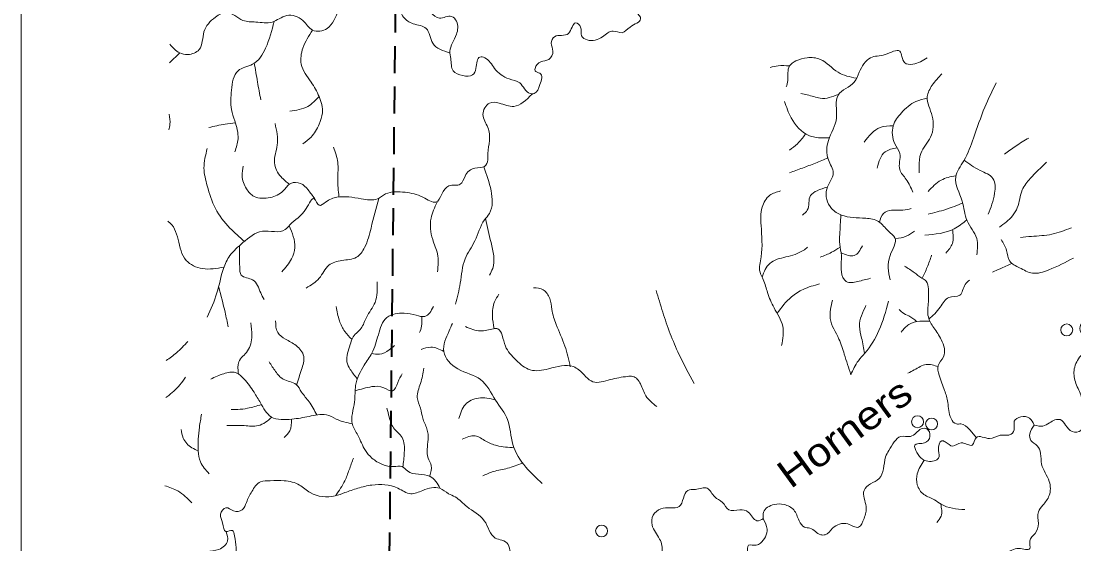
# Model space of a CAD drawing. Extents: x 788888 to 797112, y 8503144 to 8514989.
# Drawn here: x 788888 to 793559, y 8509330 to 8511652 of the extents above; entities that cross this region are included whole.
import ezdxf

# ---------------------------------------------------------------- set-up
doc = ezdxf.new("R2010")
doc.units = 0
doc.header["$LTSCALE"] = 40
doc.linetypes.add('MEDIUM_DASHED', pattern=[4.5, 3, -1.5])
for name, color, linetype, lineweight in [('15', 7, 'Continuous', 13), ('62', 7, 'Continuous', 13), ('63', 7, 'MEDIUM_DASHED', 40)]:
    doc.layers.add(name, color=color, linetype=linetype, lineweight=lineweight)

msp = doc.modelspace()

# ---------------------------------------------------------------- linework, layer by layer
at = {"layer": '15'}
msp.add_line((789591.99, 8511510.53), (789546.97, 8511465.81), dxfattribs=at)
for centre in [(793526.77, 8510280.71), (792864.9, 8509872.72), (792927.25, 8509863.12), (791463.47, 8509387.93)]:
    msp.add_circle(centre, 26.35, dxfattribs=at)
for points in [[(792948.03, 8512205.24), (792917.26, 8512179.9), (792888.48, 8512147.5), (792874.09, 8512140.3), (792838.12, 8512140.3), (792787.76, 8512118.7), (792748.2, 8512104.3), (792708.63, 8512086.3), (792683.45, 8512057.5), (792654.67, 8512035.9), (792597.12, 8512035.9), (792553.95, 8512050.3), (792532.37, 8512100.7), (792550.35, 8512136.7), (792553.95, 8512158.3), (792485.61, 8512158.3), (792449.64, 8512147.5), (792413.66, 8512115.1), (792374.1, 8512104.3), (792338.13, 8512082.7), (792312.95, 8512046.7), (792258.99, 8512064.7), (792215.82, 8512075.5), (792172.66, 8512061.1), (792169.06, 8512025.1), (792176.26, 8511985.51), (792161.87, 8511920.71), (792111.51, 8511852.31), (792050.36, 8511819.91), (791960.43, 8511812.71), (791892.08, 8511783.91), (791802.16, 8511776.71), (791744.6, 8511733.51), (791719.42, 8511701.11), (791690.65, 8511711.91), (791661.87, 8511744.31), (791633.09, 8511765.91), (791611.51, 8511758.71), (791586.33, 8511733.51), (791579.14, 8511711.91), (791615.11, 8511690.31), (791636.69, 8511661.51), (791589.93, 8511625.51), (791553.96, 8511600.32), (791514.39, 8511607.52), (791467.63, 8511582.32), (791399.28, 8511567.92), (791374.1, 8511585.92), (791370.5, 8511625.51), (791348.92, 8511643.51), (791316.55, 8511596.72), (791254.68, 8511582.32), (791240.29, 8511553.52), (791247.48, 8511517.52), (791229.5, 8511481.52), (791193.52, 8511470.72), (791168.35, 8511441.92), (791168.35, 8511431.12), (791189.93, 8511420.32), (791189.93, 8511369.92), (791164.75, 8511330.32), (791146.76, 8511330.32), (791100, 8511377.12), (791053.24, 8511395.12), (790988.49, 8511441.92), (790945.32, 8511488.72), (790923.74, 8511492.32), (790905.76, 8511441.92), (790891.37, 8511413.12), (790848.2, 8511409.52), (790805.04, 8511431.12), (790794.25, 8511485.12), (790790.65, 8511517.52), (790819.43, 8511593.12), (790819.43, 8511650.71), (790797.84, 8511672.31), (790743.89, 8511665.11), (790707.92, 8511690.31), (790689.93, 8511751.51), (790697.12, 8511819.91), (790653.96, 8511845.11), (790610.79, 8511881.11), (790560.43, 8511870.31), (790513.67, 8511938.71), (790477.7, 8511992.71), (790427.34, 8512025.1), (790380.58, 8512039.5), (790333.82, 8512050.3), (790312.23, 8512100.7), (790312.23, 8512172.7), (790305.04, 8512266.3)], [(794022.17, 8512071.41), (794015.97, 8512028.82), (794054.34, 8512024.02), (794078.32, 8512052.82), (794121.49, 8512024.02), (794179.04, 8511966.42), (794217.41, 8511932.82), (794217.41, 8511899.22), (794207.82, 8511860.82), (794164.65, 8511827.22), (794150.27, 8511764.83), (794131.08, 8511716.83), (794097.51, 8511692.83), (794073.53, 8511649.63), (794073.53, 8511620.83), (794035.16, 8511606.43), (794001.59, 8511558.43), (794001.59, 8511520.03), (793924.85, 8511515.23), (793872.09, 8511510.43), (793819.33, 8511467.24), (793795.35, 8511400.04), (793780.96, 8511347.24), (793771.37, 8511323.24), (793742.59, 8511328.04), (793718.61, 8511352.04), (793685.04, 8511347.24), (793670.65, 8511280.04), (793665.86, 8511236.84), (793694.63, 8511236.84), (793709.02, 8511227.24), (793699.43, 8511179.24), (793689.84, 8511136.04), (793675.45, 8511102.45), (793665.86, 8511064.05), (793685.04, 8511044.85), (793689.84, 8511030.45), (793675.45, 8511006.45), (793670.65, 8510972.85), (793694.63, 8510958.45), (793733, 8510972.85), (793756.98, 8510996.85), (793790.56, 8510977.65), (793819.33, 8510967.09), (793843.31, 8510938.29), (793876.89, 8510919.09), (793915.26, 8510919.09), (793958.42, 8510909.49), (793991.99, 8510890.29), (794011.18, 8510861.49), (793996.79, 8510808.69), (794006.38, 8510727.09), (794001.59, 8510626.3), (794015.97, 8510563.9), (794059.14, 8510530.3), (794063.94, 8510491.9), (794049.55, 8510458.3), (794006.38, 8510453.5), (793963.22, 8510487.1), (793910.46, 8510491.9), (793867.29, 8510487.1), (793814.54, 8510487.1), (793776.17, 8510453.5), (793752.19, 8510419.9), (793752.19, 8510391.1), (793718.61, 8510376.7), (793694.63, 8510371.9), (793685.04, 8510343.1), (793651.47, 8510328.71), (793617.9, 8510323.91), (793589.12, 8510304.71), (793589.12, 8510271.11), (793632.28, 8510266.31), (793699.43, 8510275.91), (793728.21, 8510275.91), (793728.21, 8510247.11), (793675.45, 8510218.31), (793627.49, 8510199.11), (793589.12, 8510165.51), (793560.34, 8510107.91), (793565.14, 8510050.31), (793589.12, 8509992.71), (793608.3, 8509935.12), (793617.9, 8509896.72), (793598.71, 8509877.52), (793589.12, 8509834.32), (793550.75, 8509829.52), (793521.97, 8509858.32), (793497.99, 8509882.32), (793450.03, 8509867.92), (793421.25, 8509853.52), (793382.88, 8509858.32)], [(790791, 8511510.51), (790714.06, 8511553.88), (790685.29, 8511618.68), (790627.73, 8511640.28), (790584.57, 8511669.08), (790570.18, 8511726.67), (790570.18, 8511762.67), (790505.43, 8511798.67), (790469.46, 8511798.67), (790440.68, 8511755.47), (790404.71, 8511769.87), (790375.93, 8511762.67), (790332.77, 8511741.07), (790275.22, 8511654.68), (790246.44, 8511618.68), (790181.69, 8511611.48), (790138.53, 8511654.68), (790066.58, 8511676.28), (790001.84, 8511647.48), (789929.89, 8511647.48), (789872.34, 8511654.68), (789800.4, 8511690.67), (789750.04, 8511669.08), (789699.68, 8511604.28), (789678.1, 8511525.08), (789627.74, 8511503.48), (789591.77, 8511510.68), (789547.88, 8511548.92)], [(790011.08, 8511649.28), (789973.06, 8511532.28), (789915.51, 8511460.28), (789850.76, 8511431.48), (789821.98, 8511345.08), (789821.98, 8511258.69), (789836.37, 8511208.29), (789850.76, 8511129.09), (789836.37, 8511071.49)], [(790181.69, 8511611.48), (790138.53, 8511532.28), (790131.33, 8511460.28), (790174.5, 8511381.08), (790210.47, 8511316.29), (790224.86, 8511244.29), (790210.47, 8511193.89), (790174.5, 8511136.29), (790138.53, 8511107.49)], [(792908.29, 8511489.08), (792843.55, 8511460.28), (792807.57, 8511467.48), (792785.99, 8511517.88), (792721.24, 8511503.48), (792656.5, 8511489.08), (792606.14, 8511424.28), (792584.55, 8511381.08), (792512.61, 8511323.48), (792505.42, 8511222.69), (792469.45, 8511121.89), (792469.45, 8511035.49), (792491.03, 8510977.89), (792462.25, 8510905.9), (792483.84, 8510819.5), (792527, 8510790.7), (792634.91, 8510776.3), (792692.47, 8510761.9), (792735.63, 8510718.7), (792764.41, 8510689.9), (792742.83, 8510610.7), (792742.83, 8510502.71)], [(789922.68, 8511467.05), (789937.09, 8511381.08), (789951.48, 8511301.89)], [(792593.24, 8511398.07), (792512.61, 8511424.28), (792433.48, 8511481.88), (792375.92, 8511489.08), (792325.56, 8511474.68), (792296.79, 8511453.08), (792289.59, 8511388.28), (792282.4, 8511359.48)], [(792296.79, 8511453.08), (792246.43, 8511453.08), (792210.46, 8511445.88)], [(792973.04, 8511417.08), (792929.88, 8511366.68), (792908.29, 8511316.29), (792929.88, 8511229.89), (792922.68, 8511136.29), (792879.52, 8511064.29), (792872.32, 8511006.69), (792872.32, 8510977.89)], [(793214.05, 8511377.49), (793163.69, 8511269.49), (793113.33, 8511132.69), (793070.17, 8511031.9), (793034.2, 8510959.9), (793062.97, 8510851.9), (793084.56, 8510765.5), (793127.72, 8510686.31), (793127.72, 8510614.31)], [(791155.07, 8511327.68), (791073.77, 8511273.09), (791009.02, 8511287.49), (790965.86, 8511287.49), (790937.08, 8511237.09), (790958.66, 8511179.49), (790965.86, 8511121.89), (790958.66, 8511064.29), (790958.66, 8511035.49), (790944.28, 8511006.69), (790901.11, 8510999.49), (790857.95, 8510963.49), (790836.36, 8510927.5), (790786, 8510920.3), (790728.45, 8510848.3), (790670.9, 8510869.9), (790591.76, 8510891.5), (790505.43, 8510884.3), (790469.46, 8510862.7), (790397.52, 8510862.7), (790289.6, 8510869.9), (790239.24, 8510848.3), (790210.47, 8510833.9), (790188.89, 8510862.7), (790152.91, 8510819.5), (790080.97, 8510747.5), (790059.39, 8510725.9), (789958.67, 8510718.7), (789872.34, 8510668.3), (789814.79, 8510610.7), (789786.01, 8510553.11), (789757.23, 8510445.11), (789714.07, 8510337.11)], [(792513.92, 8511326.3), (792433.48, 8511309.09), (792404.7, 8511316.29), (792347.15, 8511330.68)], [(790209.99, 8511317.19), (790160.11, 8511273.09), (790080.97, 8511251.49)], [(792472.23, 8511133.5), (792383.12, 8511143.49), (792303.98, 8511222.69), (792275.2, 8511294.69)], [(792907.99, 8511309.27), (792857.93, 8511294.69), (792793.19, 8511244.29), (792757.22, 8511186.69), (792764.41, 8511107.49), (792785.99, 8511064.29), (792785.99, 8510992.29), (792814.77, 8510949.1), (792843.55, 8510891.5)], [(789544.49, 8511238.32), (789548.6, 8511193.89), (789543.74, 8511168.98)], [(789838.71, 8511199.65), (789793.2, 8511193.89), (789721.26, 8511179.49)], [(790079.11, 8510927.04), (790041.4, 8510959.88), (790012.63, 8511022.27), (790024.62, 8511101.47), (790015.03, 8511197.47)], [(792757.22, 8511186.69), (792699.66, 8511179.49), (792627.72, 8511114.69)], [(792366.45, 8511147.91), (792332.76, 8511107.49), (792296.79, 8511078.69)], [(790298.5, 8510871.21), (790293.2, 8510952.68), (790293.2, 8511024.68), (790274.02, 8511091.87)], [(792773.71, 8511088.6), (792721.24, 8511071.49), (792685.27, 8510999.49)], [(793357.94, 8511132.69), (793300.38, 8511096.7), (793250.02, 8511060.7)], [(789879.18, 8510673.6), (789814.79, 8510733.1), (789750.04, 8510819.5), (789714.07, 8510920.3), (789699.68, 8510999.49), (789714.07, 8511085.89)], [(792468.41, 8511044.83), (792411.89, 8511021.09), (792354.34, 8510999.49), (792296.79, 8510977.89)], [(790190.62, 8510863.78), (790161.31, 8510902.28), (790127.73, 8510931.08), (790084.57, 8510931.08), (790051, 8510897.48), (789993.44, 8510868.68), (789921.5, 8510873.48), (789887.93, 8510907.08), (789868.74, 8510964.68), (789873.54, 8511007.87)], [(790940.78, 8511004.13), (790973.05, 8510898.7), (790965.86, 8510797.9), (790944.28, 8510769.1), (790901.11, 8510675.5), (790857.95, 8510596.3), (790836.36, 8510488.31), (790814.78, 8510394.71)], [(793071.31, 8511034.53), (793142.11, 8510988.7), (793199.66, 8510952.7), (793206.86, 8510887.9), (793178.08, 8510794.3)], [(793437.07, 8511024.7), (793365.13, 8510952.7), (793329.16, 8510902.3), (793307.58, 8510823.1), (793285.99, 8510787.1), (793228.44, 8510736.71)], [(793034.06, 8510965.35), (792969.45, 8510945.5), (792911.9, 8510895.1)], [(792463.79, 8510914.78), (792419.09, 8510898.7), (792390.31, 8510877.1), (792375.92, 8510812.3), (792354.34, 8510790.7)], [(790475.07, 8510863.99), (790440.68, 8510733.1), (790411.91, 8510646.7), (790375.93, 8510603.5), (790311.19, 8510589.1), (790253.63, 8510567.51), (790210.47, 8510509.91), (790152.91, 8510466.71)], [(792262.02, 8510211.12), (792266.82, 8510297.51), (792228.45, 8510379.11), (792199.67, 8510446.31), (792180.49, 8510503.91), (792166.1, 8510537.51), (792170.9, 8510604.7), (792170.9, 8510743.9), (792175.69, 8510825.5), (792209.27, 8510878.3), (792257.23, 8510897.5)], [(790733.93, 8510847.94), (790706.87, 8510776.3), (790714.06, 8510682.7), (790735.64, 8510617.9), (790735.64, 8510538.71)], [(792696.06, 8510758.31), (792714.05, 8510797.9), (792750.02, 8510812.3), (792800.38, 8510812.3), (792836.35, 8510819.5)], [(793065.1, 8510843.46), (792991.03, 8510815.9), (792911.9, 8510794.3)], [(789788.22, 8510559.5), (789692.49, 8510553.11), (789620.54, 8510589.1), (789584.57, 8510682.7), (789541.41, 8510761.9), (789539.31, 8510763.3)], [(790948.25, 8510775.39), (790973.05, 8510668.3), (790980.25, 8510553.11), (790965.86, 8510524.31)], [(792525.26, 8510791.11), (792519.81, 8510704.3), (792519.81, 8510661.1), (792527, 8510610.7), (792527, 8510538.71), (792548.58, 8510495.51), (792598.94, 8510495.51), (792656.5, 8510509.91)], [(793083.67, 8510768.97), (793027, 8510729.51), (792897.51, 8510700.71)], [(790077.33, 8510743.86), (790102.55, 8510646.7), (790088.17, 8510596.3), (790045, 8510538.71)], [(792767.89, 8510685.13), (792814.77, 8510697.1), (792850.74, 8510718.7)], [(793019.8, 8510726.54), (793019.81, 8510664.71), (792991.03, 8510621.51)], [(793547.39, 8510734.3), (793461.06, 8510705.5), (793369.93, 8510695.9), (793321.97, 8510691.1)], [(793556.98, 8510599.9), (793446.67, 8510547.11), (793374.73, 8510532.71), (793317.17, 8510556.71), (793274.01, 8510585.51), (793259.62, 8510633.5), (793235.64, 8510681.5)], [(789857.29, 8510655.96), (789857.95, 8510560.31), (789865.15, 8510524.31), (789915.51, 8510502.71), (789951.48, 8510445.11), (789965.86, 8510416.31)], [(792175.16, 8510515.47), (792209.27, 8510575.91), (792281.21, 8510604.7), (792357.95, 8510633.5), (792377.13, 8510647.9)], [(792521.07, 8510647.85), (792483.84, 8510625.1), (792433.48, 8510603.5)], [(792525.16, 8510623.59), (792584.55, 8510610.7), (792620.53, 8510653.9)], [(792885.01, 8510510.43), (792908.06, 8510559.09), (792927.25, 8510611.89)], [(793282.98, 8510576.15), (793230.84, 8510551.91), (793197.27, 8510537.51)], [(793124.92, 8509802.74), (793095.11, 8509839.11), (793056.74, 8509863.11), (793037.56, 8509863.11), (793013.58, 8509887.11), (792999.19, 8509959.11), (792984.8, 8510011.9), (792960.82, 8510079.1), (792956.02, 8510122.3), (792980.01, 8510160.7), (792970.41, 8510237.5), (792936.84, 8510290.3), (792912.86, 8510338.3), (792912.86, 8510405.49), (792912.86, 8510463.09), (792903.27, 8510496.69), (792884.08, 8510511.09), (792850.51, 8510535.09), (792807.34, 8510563.89)], [(790379.71, 8510063.12), (790348.36, 8510105.5), (790333.97, 8510139.1), (790348.36, 8510215.9), (790357.95, 8510244.7), (790396.32, 8510287.89), (790420.3, 8510335.89), (790458.67, 8510403.09), (790468.26, 8510494.29)], [(792242.44, 8510354.86), (792305.19, 8510427.11), (792357.95, 8510460.71), (792429.89, 8510484.71)], [(792914.57, 8510327.72), (792965.62, 8510381.49), (793003.99, 8510424.69), (793051.95, 8510434.29), (793075.93, 8510482.29), (793095.11, 8510501.49)], [(789765.57, 8510470.35), (789793.2, 8510358.71), (789807.59, 8510293.91)], [(790987.01, 8510285.96), (790979.06, 8510343.1), (790988.65, 8510405.5), (791007.83, 8510439.1)], [(791324.54, 8510117.39), (791300.4, 8510208.71), (791262.03, 8510304.71), (791242.84, 8510371.9), (791233.25, 8510419.9), (791204.47, 8510458.3), (791161.31, 8510467.9)], [(791873.54, 8510043.12), (791806.39, 8510172.72), (791768.02, 8510263.91), (791734.45, 8510359.91), (791705.67, 8510455.91)], [(792568.98, 8510081.52), (792540.2, 8510172.72), (792516.22, 8510239.91), (792477.85, 8510331.11), (792487.44, 8510412.71)], [(792568.98, 8510081.52), (792602.55, 8510143.92), (792631.33, 8510177.52), (792693.68, 8510278.31), (792736.84, 8510407.91)], [(792630.03, 8510175.8), (792616.94, 8510244.71), (792607.35, 8510297.51), (792636.12, 8510388.71)], [(790355.42, 8510238.99), (790324.37, 8510273.5), (790300.39, 8510321.49), (790286.01, 8510383.89)], [(790747.76, 8509577.09), (790703.27, 8509630.31), (790650.51, 8509639.91), (790602.55, 8509654.31), (790578.57, 8509673.51), (790540.2, 8509673.51), (790492.24, 8509683.11), (790444.28, 8509711.91), (790415.5, 8509745.51), (790381.93, 8509812.71), (790357.95, 8509860.71), (790367.54, 8509961.5), (790372.34, 8510033.5), (790410.71, 8510124.7), (790444.28, 8510177.5), (790473.06, 8510259.1), (790511.42, 8510335.89), (790588.16, 8510355.09), (790640.92, 8510345.49), (790679.29, 8510340.69), (790717.66, 8510383.89)], [(792860.19, 8510318.3), (792826.53, 8510343.1), (792797.75, 8510357.49), (792783.36, 8510371.89)], [(789851.94, 8510085.57), (789854.35, 8510139.1), (789892.72, 8510187.1), (789911.91, 8510254.3), (789907.11, 8510311.89)], [(790110.35, 8510036), (790132.53, 8510105.5), (790142.12, 8510163.1), (790108.55, 8510211.1), (790060.59, 8510239.9), (790027.01, 8510268.7), (790017.42, 8510321.49)], [(790665.3, 8510337.71), (790664.9, 8510297.49), (790655.31, 8510268.7)], [(791199.68, 8509599.13), (791127.74, 8509671.12), (791070.18, 8509771.92), (791046.2, 8509882.32), (790993.44, 8509968.72), (790926.3, 8510059.91), (790825.58, 8510107.91), (790763.23, 8510184.71), (790787.21, 8510275.91), (790801.6, 8510309.51)], [(791708.07, 8509939.92), (791660.11, 8509987.91), (791636.13, 8510040.71), (791602.55, 8510074.31), (791578.57, 8510074.31), (791501.83, 8510059.91), (791425.1, 8510050.31), (791362.75, 8510103.11), (791338.77, 8510117.51), (791228.45, 8510107.91), (791146.92, 8510103.11), (791084.57, 8510146.31), (791036.61, 8510208.71), (791022.22, 8510256.71), (791003.04, 8510285.51), (790983.85, 8510285.51), (790926.3, 8510275.91), (790859.15, 8510295.11)], [(792918.06, 8510319.48), (792874.49, 8510319.1), (792826.53, 8510304.7), (792792.96, 8510271.1)], [(789532.56, 8510144.46), (789577.38, 8510178.72), (789627.74, 8510229.11)], [(790443.37, 8510175.59), (790477.85, 8510172.7), (790521.02, 8510191.9), (790545, 8510211.1)], [(790763.21, 8510185.13), (790705.68, 8510203.91), (790662.51, 8510194.31)], [(790199.81, 8509903.13), (790166.1, 8509961.5), (790132.53, 8510004.7), (790108.55, 8510038.3), (790051, 8510062.3), (790017.42, 8510095.9), (789988.65, 8510139.1)], [(790701.06, 8509632.56), (790708.07, 8509678.31), (790693.68, 8509711.91), (790693.68, 8509793.51), (790688.88, 8509841.51), (790669.7, 8509889.51), (790660.1, 8509932.7), (790645.72, 8509980.7), (790660.1, 8510043.1), (790674.49, 8510110.3)], [(792955.82, 8510117.29), (792903.27, 8510127.1), (792850.51, 8510103.1), (792821.73, 8510088.7)], [(789530.77, 8509980.46), (789535.41, 8509984.07), (789592.97, 8510036.86), (789616.95, 8510070.46)], [(790356.69, 8509863.45), (790286.01, 8509884.71), (790242.84, 8509903.91), (790204.47, 8509903.91), (790127.73, 8509889.51), (790089.36, 8509884.71), (789998.24, 8509894.31), (789950.28, 8509956.7), (789921.5, 8510004.7), (789878.33, 8510062.3), (789839.97, 8510091.1), (789787.21, 8510086.3), (789729.65, 8510062.3)], [(790370.26, 8510009.63), (790444.28, 8510028.7), (790497.04, 8510023.9), (790535.4, 8510009.5), (790559.39, 8510047.9), (790578.57, 8510086.3)], [(790992.73, 8509969.8), (790916.71, 8509978.32), (790859.15, 8509949.52), (790830.38, 8509887.12)], [(789954.54, 8509949.57), (789892.72, 8509932.7), (789849.56, 8509927.91), (789820.78, 8509927.91)], [(790582.15, 8509672.12), (790588.16, 8509735.91), (790578.57, 8509803.11), (790540.2, 8509846.31), (790521.02, 8509894.31), (790511.42, 8509932.7)], [(789722.47, 8509642.32), (789684.1, 8509695.12), (789674.51, 8509743.12), (789679.3, 8509848.72), (789688.9, 8509906.32)], [(790001, 8509892.59), (789940.68, 8509855.91), (789878.33, 8509855.91), (789801.6, 8509855.91)], [(790088.33, 8509884.6), (790079.77, 8509831.91), (790055.79, 8509803.11)], [(793382.88, 8509858.32), (793361.3, 8509889.51), (793322.93, 8509894.31), (793294.15, 8509875.11), (793294.15, 8509846.31), (793279.76, 8509817.51), (793231.8, 8509812.71), (793183.84, 8509798.31), (793126.29, 8509803.11), (793107.1, 8509769.51), (793059.14, 8509779.11), (793020.77, 8509764.71), (792987.2, 8509783.91), (792972.81, 8509788.71), (792958.42, 8509745.51), (792958.42, 8509711.91), (792910.46, 8509697.51), (792886.48, 8509707.11), (792862.5, 8509735.91), (792852.91, 8509769.51), (792896.07, 8509779.11), (792920.05, 8509807.91), (792905.66, 8509841.51), (792881.68, 8509841.51), (792857.7, 8509822.31), (792833.72, 8509807.91), (792790.56, 8509807.91), (792761.78, 8509783.91), (792737.8, 8509745.51), (792723.41, 8509716.71), (792713.82, 8509663.91), (792694.63, 8509620.72), (792656.27, 8509596.72), (792627.49, 8509567.92), (792637.08, 8509495.92), (792627.49, 8509443.12), (792603.51, 8509404.72), (792555.55, 8509419.12), (792488.4, 8509399.92), (792454.83, 8509371.12), (792435.64, 8509371.12), (792411.66, 8509385.52), (792387.68, 8509399.92), (792363.7, 8509404.72), (792339.72, 8509433.52), (792315.74, 8509481.52), (792272.57, 8509505.52), (792229.41, 8509505.52), (792181.45, 8509471.92), (792181.45, 8509438.32)], [(789674.51, 8509743.07), (789645.73, 8509757.52), (789607.36, 8509800.72), (789597.77, 8509839.12)], [(793382.88, 8509858.32), (793362.73, 8509818.94), (793367.53, 8509790.14), (793396.31, 8509766.15), (793410.69, 8509732.55), (793415.49, 8509684.55), (793449.06, 8509607.75), (793449.06, 8509545.35), (793420.29, 8509502.15), (793401.1, 8509473.35), (793401.1, 8509420.55), (793386.71, 8509377.36), (793362.73, 8509343.76), (793362.73, 8509310.16), (793314.77, 8509310.16), (793257.22, 8509286.16), (793214.05, 8509247.76), (793209.26, 8509194.96), (793194.87, 8509137.36), (793175.68, 8509103.76), (793180.48, 8509060.57), (793218.85, 8509031.77), (793233.24, 8509012.57), (793218.85, 8508964.57), (793180.48, 8508902.17), (793146.91, 8508820.57), (793127.72, 8508729.37), (793137.31, 8508700.58), (793170.89, 8508690.98), (793204.46, 8508662.18), (793223.65, 8508585.38), (793228.44, 8508508.58), (793238.03, 8508455.78), (793238.03, 8508398.18), (793209.26, 8508364.58), (793214.05, 8508326.19), (793257.22, 8508330.99), (793295.59, 8508345.39), (793329.16, 8508330.99), (793362.73, 8508297.39), (793410.69, 8508278.19), (793434.68, 8508254.19), (793444.27, 8508196.59), (793449.06, 8508153.39), (793444.27, 8508110.19), (793425.08, 8508062.19), (793425.08, 8508004.59), (793410.69, 8507947), (793372.33, 8507927.8), (793353.14, 8507927.8), (793333.96, 8507894.2), (793329.16, 8507855.8), (793319.57, 8507822.2), (793333.96, 8507774.2), (793305.18, 8507759.8), (793257.22, 8507764.6), (793199.66, 8507783.8), (793156.5, 8507793.4), (793127.72, 8507807.8)], [(791076.23, 8509757.26), (790998.24, 8509767.12), (790950.28, 8509786.32), (790902.32, 8509810.32), (790844.76, 8509795.92)], [(790284.09, 8509544.88), (790324.37, 8509611.11), (790343.56, 8509659.11), (790362.74, 8509711.91)], [(791112.22, 8509689.26), (791046.2, 8509666.32), (790983.85, 8509651.92), (790935.89, 8509632.72)], [(792894.25, 8509702.35), (792863.93, 8509641.35), (792863.93, 8509593.35), (792892.71, 8509550.15), (792940.67, 8509526.15), (792969.45, 8509506.95), (793074.96, 8509482.95)], [(792181.45, 8509443.12), (792152.67, 8509433.52), (792114.3, 8509471.92), (792075.93, 8509481.52), (792027.97, 8509481.52), (791999.19, 8509515.12), (791965.62, 8509539.12), (791932.05, 8509577.52), (791879.29, 8509572.72), (791845.72, 8509567.92), (791826.53, 8509534.32), (791807.35, 8509495.92), (791768.98, 8509491.12), (791725.82, 8509486.32), (791692.24, 8509457.52), (791687.45, 8509414.32), (791721.02, 8509351.92), (791730.61, 8509294.32), (791721.02, 8509275.13), (791663.47, 8509270.33), (791581.93, 8509294.32), (791514.79, 8509289.52), (791452.44, 8509260.73), (791423.66, 8509217.53), (791438.05, 8509179.13), (791466.82, 8509159.93), (791457.23, 8509126.33), (791394.88, 8509107.13), (791342.12, 8509073.53), (791313.35, 8509020.73), (791303.76, 8508982.33), (791265.39, 8508967.93), (791212.63, 8508967.93), (791183.85, 8508996.73), (791183.85, 8509049.53), (791193.44, 8509092.73), (791164.67, 8509164.73), (791121.5, 8509227.13), (791078.34, 8509275.13), (791059.15, 8509294.32), (791049.56, 8509327.92), (791020.78, 8509347.12), (790992.01, 8509356.72), (790943.08, 8509433.52), (790866.34, 8509495.92), (790813.58, 8509539.12), (790784.81, 8509553.52), (790746.44, 8509577.52), (790669.7, 8509567.92), (790616.94, 8509553.52), (790559.39, 8509577.52), (790444.28, 8509591.92), (790381.93, 8509577.52), (790324.38, 8509558.32), (790281.21, 8509543.92), (790170.9, 8509558.32), (790122.94, 8509591.92), (790055.79, 8509611.12), (789993.44, 8509611.12), (789950.28, 8509606.32), (789911.91, 8509563.12), (789887.93, 8509515.12), (789868.75, 8509481.52), (789830.38, 8509476.72), (789796.8, 8509491.12), (789772.82, 8509462.32), (789782.41, 8509423.92), (789796.8, 8509385.52), (789825.58, 8509390.32), (789835.17, 8509366.32), (789839.97, 8509270.33), (789796.8, 8509183.93), (789744.05, 8509126.33), (789720.07, 8509063.93), (789748.84, 8509044.73), (789763.23, 8509001.53), (789806.4, 8508977.53), (789839.97, 8508943.93), (789883.13, 8508915.14), (789897.52, 8508881.54), (789931.1, 8508867.14), (789974.26, 8508804.74), (790007.83, 8508723.14), (789988.65, 8508627.14), (789945.48, 8508526.35), (789907.11, 8508487.95), (789873.54, 8508454.35), (789825.58, 8508372.75), (789796.8, 8508305.55), (789734.45, 8508247.95), (789700.88, 8508199.96)], [(789645.73, 8509512.73), (789583.38, 8509565.53), (789526.5, 8509588.71)], [(792967.76, 8509507.4), (792969.45, 8509454.15), (792950.27, 8509425.35)], [(792181.45, 8509438.32), (792197.27, 8509396.56), (792168.5, 8509334.16), (792149.31, 8509324.56), (792115.74, 8509324.56), (792110.94, 8509286.16), (792096.55, 8509252.56), (792058.18, 8509247.76), (792058.18, 8509190.16), (792091.76, 8509151.76), (792106.15, 8509074.96), (792096.55, 8509007.77), (792058.18, 8508959.77), (792039, 8508873.37), (792048.59, 8508762.97), (792048.59, 8508700.58), (792096.55, 8508662.18), (792134.92, 8508657.38), (792168.5, 8508686.18), (792187.68, 8508671.78), (792182.88, 8508604.58), (792173.29, 8508542.18), (792154.11, 8508518.18), (792154.11, 8508479.78), (792168.5, 8508460.58), (792192.48, 8508460.58), (792211.66, 8508431.78), (792226.05, 8508393.38), (792226.05, 8508350.19), (792226.05, 8508302.19), (792221.25, 8508268.59), (792250.03, 8508234.99), (792254.83, 8508182.19), (792259.62, 8508129.39), (792278.81, 8508076.59), (792264.42, 8508023.79), (792264.42, 8507947), (792278.81, 8507899), (792297.99, 8507860.6), (792293.19, 8507827), (792259.62, 8507745.4), (792245.23, 8507668.6), (792264.42, 8507596.61), (792288.4, 8507519.81), (792254.83, 8507428.61), (792245.23, 8507390.21), (792245.23, 8507318.21), (792240.44, 8507241.42), (792221.25, 8507203.02), (792154.11, 8507188.62), (792115.74, 8507174.22)], [(789797.78, 8509384.22), (789804, 8509344.72), (789765.63, 8509306.32), (789712.87, 8509296.72), (789626.54, 8509263.12), (789522.74, 8509244.58)]]:
    msp.add_spline(points, degree=3, dxfattribs=at)
at = {"layer": '62'}
msp.add_lwpolyline([(788888.17, 8503144.43), (797111.52, 8503144.43), (797111.52, 8514986.23), (788888.17, 8514986.23)], close=True, dxfattribs=at)
at = {"layer": '63'}
msp.add_lwpolyline([(795985.61, 8513296.58), (795924.11, 8507761.4), (790507.28, 8507821.14), (790567.65, 8513356.12), (795985.61, 8513296.58)], close=True, dxfattribs=at)

# ---------------------------------------------------------------- texts
at = {"layer": '15', "width": 1.15}
msp.add_text('Horners', height=125, rotation=36.11, dxfattribs=at).set_placement((792301.76, 8509572.23))

doc.saveas('drawing.dxf')
